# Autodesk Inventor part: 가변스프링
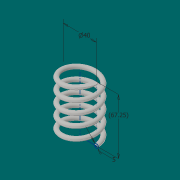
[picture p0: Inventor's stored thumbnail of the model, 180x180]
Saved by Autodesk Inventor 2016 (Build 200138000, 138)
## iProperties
Created: 2018-08
Part Number: 가변스프링
Material: 일반
Document SubType Name: Modeling
Designer: 605-04
Density: 1 g/cm^3
Appearance: 기본값
Author: 605-04
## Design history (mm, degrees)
sketch "스케치1"
  geometry: L1 (0, 0)-(20, 0); L2 (20, 0)-(20, 67.25); L3 (20, 67.25)-(0, 67.25); L4 (0, 67.25)-(0, 0); C1 r 2.5 at (20, 0)
  constraints: 8 end point, 2 parallel, 1 centre point, 1 coincident, 1 horizontal, 1 perpendicular
  dimensions: "d0" = 67.25 distance of L1.end L2.end (derived); "d1" = 40 diameter of L2 L4; "d2" = 5 diameter of C1
feature "코일1" pitch "d3" = 10; turns "d5" = 5; dims "d4" = 67.25 (= d0), "d6" = 0, angle "d7" = 90 deg, angle "d8" = 90 deg, "d9" = 0, "d10" = 0
sketch "스케치2"
  geometry: L1 (-22.5, 0)-(-17.5, 0) reference; 1 further point
  constraints: 1 horizontal alignment
extrude "돌출1" cut sketch "스케치2" stored distance "d11" = 10; taper "d12" = 0 deg
node "작업 평면1"
sketch "스케치3"
  geometry: L1 (2.5, 0)-(-2.5, 0) reference; 1 further point
  constraints: 1 horizontal alignment
extrude "돌출2" cut sketch "스케치3" stored distance "d14" = 10; taper "d15" = 0 deg
node "솔리드1"
node "절단 모서리 투영1"
node "절단 모서리 투영2"
other parameters: "d13" = 90 deg
